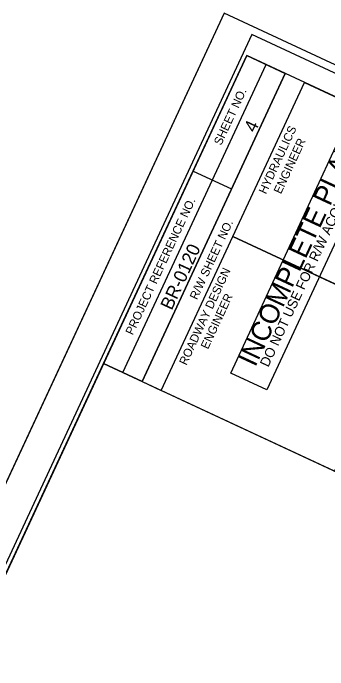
# Model space of a CAD drawing. Extents: x 2532214 to 2534758, y 714172 to 717266.
# Drawn here: x 2532799.9 to 2532985.3, y 716233.1 to 716619.6 of the extents above; entities that cross this region are included whole.
import ezdxf

# ---------------------------------------------------------------- set-up
doc = ezdxf.new("R2010")
doc.units = 0
for name, color, linetype in [('Arrowhead Terminators', 7, 'Continuous'), ('Dimension Lines CELL', 7, 'Continuous'), ('Mis Existing Structures', 7, 'Continuous'), ('Mis Ground Lines', 7, 'Continuous'), ('Mis Object Lines', 7, 'Continuous'), ('Structural Steel Angle 3 x 3', 7, 'Continuous'), ('Structural Steel Lines', 7, 'Continuous'), ('Text', 7, 'Continuous')]:
    doc.layers.add(name, color=color, linetype=linetype)

msp = doc.modelspace()

# ---------------------------------------------------------------- linework, layer by layer
at = {"layer": 'Arrowhead Terminators'}
msp.add_line((2532924.28, 716619.61), (2532214.14, 715093.22), dxfattribs=at)
at = {"layer": 'Dimension Lines CELL'}
msp.add_lwpolyline([(2533392.43, 716327.91), (2533206.82, 715928.98), (2532801.87, 715058.57), (2532325.86, 715280.03), (2532853.13, 716413.33), (2533042.37, 716325.28), (2533105.67, 716461.33), (2533324.42, 716359.55)], close=True, dxfattribs=at)
at = {"layer": 'Mis Existing Structures'}
msp.add_lwpolyline([(2533194.3, 714651.54), (2533897.06, 716162.07), (2532940.52, 716607.1), (2532237.75, 715096.57)], close=True, dxfattribs=at)
at = {"layer": 'Mis Ground Lines'}
msp.add_lwpolyline([(2533206.95, 714631.32), (2533917.09, 716157.71), (2532924.28, 716619.61), (2532214.14, 715093.22)], close=True, dxfattribs=at)
at = {"layer": 'Mis Object Lines'}
msp.add_lwpolyline([(2532949.37, 716397.83), (2532928.06, 716407.74), (2532990.07, 716541.03), (2533011.38, 716531.11)], close=True, dxfattribs=at)
at = {"layer": 'Structural Steel Angle 3 x 3'}
msp.add_lwpolyline([(2532325.86, 715280.03), (2532853.13, 716413.33), (2533042.37, 716325.28), (2533126.76, 716506.66), (2533345.52, 716404.88), (2533138.82, 715960.61), (2533229.49, 715918.43), (2532824.53, 715048.02)], close=True, dxfattribs=at)
at = {"layer": 'Structural Steel Lines'}
for p, q in [((2532864.5, 716408.03), (2532948.89, 716589.41)), ((2532875.84, 716402.76), (2532960.22, 716584.14)), ((2532905.92, 716526.69), (2532928.59, 716516.14)), ((2532929.37, 716488.2), (2533031.33, 716440.77)), ((2532875.84, 716402.76), (2532887.17, 716397.49))]:
    msp.add_line(p, q, dxfattribs=at)
for points in [[(2532937.51, 716594.71), (2532304.77, 715234.69), (2533256.78, 714791.77), (2533889.52, 716151.79)], [(2532853.13, 716413.33), (2532937.51, 716594.71), (2532960.22, 716584.14), (2532875.84, 716402.76)], [(2532929.37, 716488.2), (2532971.56, 716578.87), (2533073.56, 716531.41), (2533031.38, 716440.74)], [(2532887.17, 716397.49), (2532929.37, 716488.2), (2533031.38, 716440.74), (2532989.17, 716350.03)]]:
    msp.add_lwpolyline(points, close=True, dxfattribs=at)

# ---------------------------------------------------------------- texts
at = {"layer": 'Mis Object Lines'}
for s, height, p in [('INCOMPLETE PLANS', 11.52, (2532942.54, 716410.88)), ('DO NOT USE FOR R/W ACQUISITION', 5.76, (2532950.21, 716410.9))]:
    msp.add_text(s, height=height, rotation=65.05, dxfattribs=at).set_placement(p)
at = {"layer": 'Structural Steel Lines'}
for s, height, p in [('SHEET NO.', 5, (2532922.42, 716541.4)), ('HYDRAULICS', 5, (2532948.84, 716512.73)), ('ENGINEER', 5, (2532957.65, 716512.82)), ('PROJECT REFERENCE NO.', 5.0001, (2532870.38, 716429.78)), ('R/W SHEET NO.', 5.0001, (2532908.22, 716450.56)), ('ROADWAY DESIGN', 5.0001, (2532901.97, 716412)), ('ENGINEER', 5, (2532914.7, 716421.46))]:
    msp.add_text(s, height=height, rotation=65.05, dxfattribs=at).set_placement(p)
at = {"layer": 'Text'}
for s, p in [('4', (2532942.54, 716548.86)), ('BR-0120', (2532893.32, 716444.32))]:
    msp.add_text(s, height=7.75, rotation=65.05, dxfattribs=at).set_placement(p)

doc.saveas('drawing.dxf')
